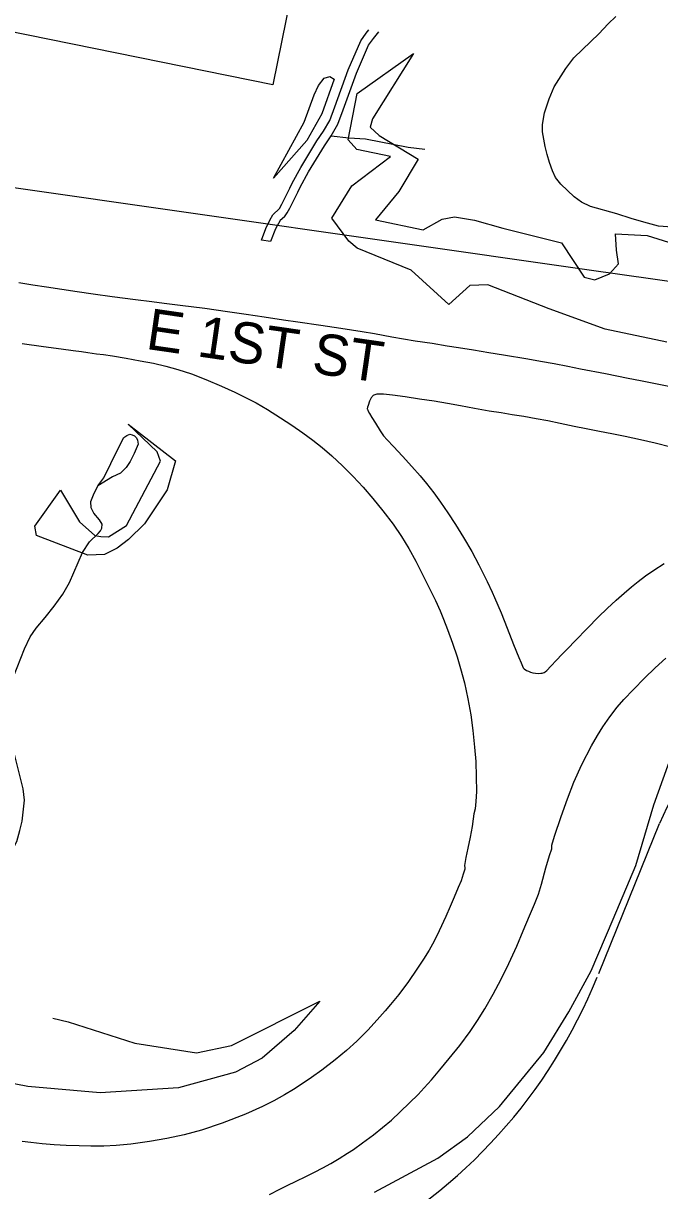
# Model space of a CAD drawing. Extents: x 1517485 to 1521905, y 636528 to 640355.
# Drawn here: x 1520638.4 to 1520886.6, y 638044.5 to 638499.8 of the extents above; entities that cross this region are included whole.
import ezdxf

# ---------------------------------------------------------------- set-up
doc = ezdxf.new("R2010")
doc.units = 0
for name, color, linetype in [('Exist Building', 7, 'Continuous'), ('Exist Hydro Stream or Body of Water', 7, 'Continuous'), ('Exist Right of Way Line', 7, 'Continuous'), ('Exist Roads EOP', 7, 'Continuous'), ('Exist Roads EOP Text', 7, 'Continuous'), ('Exist Vegetation Woods Line', 7, 'Continuous')]:
    doc.layers.add(name, color=color, linetype=linetype)

msp = doc.modelspace()

# ---------------------------------------------------------------- linework, layer by layer
at = {"layer": 'Exist Building'}
msp.add_lwpolyline([(1520578.55, 638507.74), (1520628.44, 638753.1), (1520785.56, 638721.15), (1520735.68, 638475.79)], close=True, dxfattribs=at)
at = {"layer": 'Exist Hydro Stream or Body of Water'}
for p, q in [((1520740.26, 638424.4), (1520741.25, 638425.86)), ((1520734.82, 638414.67), (1520731.3, 638415.27))]:
    msp.add_line(p, q, dxfattribs=at)
for points in [[(1520866.57, 638499.66), (1520869.57, 638502.49)], [(1520738.25, 638427.6), (1520739.26, 638429.35), (1520742.29, 638435.51), (1520743.29, 638437.53), (1520746.58, 638443.61), (1520752.94, 638453.93), (1520755.49, 638457.82), (1520757.92, 638461.98), (1520759.85, 638467.24), (1520765.15, 638481.67), (1520770.02, 638492.94), (1520772.17, 638496.03), (1520773.18, 638497.28)], [(1520741.25, 638425.86), (1520742.33, 638427.71), (1520745.4, 638433.98), (1520746.38, 638435.93), (1520749.59, 638441.87), (1520755.86, 638452.06), (1520758.44, 638455.99), (1520761.07, 638460.49), (1520763.1, 638466.04), (1520768.38, 638480.38), (1520773.07, 638491.24), (1520774.95, 638493.94), (1520777.06, 638496.55)], [(1520891.56, 638420.25), (1520886.13, 638420.7), (1520880.48, 638422.22), (1520875.53, 638423.69), (1520869.88, 638425.48), (1520859.66, 638428.33), (1520856.1, 638430.02), (1520853.26, 638432.13), (1520848.04, 638437.03), (1520845.95, 638439.72), (1520844.8, 638442.29), (1520843.69, 638445.51), (1520842.75, 638448.7), (1520842, 638451.81), (1520841.39, 638454.65), (1520840.88, 638457.53), (1520840.87, 638460.33), (1520841.75, 638464.85), (1520843.47, 638470.4), (1520845.53, 638475.09), (1520850.06, 638482.2), (1520853.09, 638486.31), (1520856.55, 638489.59), (1520862.85, 638495.74), (1520866.57, 638499.66)], [(1520758.44, 638455.99), (1520765.42, 638455.22), (1520771.8, 638454.72), (1520788.46, 638451.49), (1520795.05, 638450.71)], [(1520731.3, 638415.27), (1520733.01, 638419.8), (1520734.59, 638423.02), (1520735.68, 638425.14), (1520738.25, 638427.6)], [(1520740.26, 638424.4), (1520738.51, 638422.85), (1520736.76, 638419.71), (1520734.82, 638414.67)], [(1520665.7, 638315.85), (1520667.46, 638319.42), (1520669.75, 638322.58), (1520675.21, 638333.71), (1520677.51, 638338.26), (1520678.77, 638339.1), (1520679.87, 638339.64), (1520680.82, 638339.32), (1520681.72, 638338.87), (1520682.54, 638338.16), (1520682.92, 638337.19), (1520683.17, 638335.69), (1520681.55, 638332.02), (1520680.05, 638328.92), (1520678.46, 638326.54), (1520676.33, 638324.4), (1520673.21, 638322.96), (1520667.46, 638319.42)], [(1520668.1, 638306.19), (1520665.89, 638308.73), (1520664.82, 638310.89), (1520664.64, 638313.26), (1520665.7, 638315.85)], [(1520650.38, 638272.52), (1520653.83, 638277.19), (1520656.35, 638281.74), (1520661.38, 638293.42), (1520664.12, 638297.58), (1520667.57, 638300.89), (1520668.5, 638301.92), (1520668.93, 638302.93), (1520669.09, 638304.44), (1520668.1, 638306.19)], [(1520628.72, 638168.47), (1520630.1, 638171.66), (1520630.45, 638173.94), (1520631.42, 638175.53), (1520633.87, 638177.73), (1520634.78, 638178.74), (1520635.76, 638180.71), (1520636.98, 638184.96), (1520637.84, 638188.69), (1520638.84, 638196.88), (1520638.29, 638201.28), (1520634.9, 638214.77), (1520632.9, 638223.52), (1520631.75, 638232.09), (1520631.65, 638236.97), (1520632.89, 638240.82), (1520635.98, 638248.57), (1520638.83, 638255.82), (1520641.07, 638260.51), (1520643.43, 638263.96), (1520646.83, 638268.07), (1520650.38, 638272.52)]]:
    msp.add_lwpolyline(points, dxfattribs=at)
at = {"layer": 'Exist Right of Way Line'}
for p, q in [((1520592.71, 638441.73), (1520859.18, 638403.68)), ((1520859.18, 638403.68), (1520978.8, 638386.68)), ((1520862.88, 638129.25), (1520886.64, 638187.72))]:
    msp.add_line(p, q, dxfattribs=at)
for centre, radius, start, end in [((1520977.43, 638150.83), 98, 95.5211, 157.8844), ((1520668.65, 638206.43), 209, 297.9565, 337.8844)]:
    msp.add_arc(centre, radius, start, end, dxfattribs=at)
at = {"layer": 'Exist Roads EOP'}
for points in [[(1520636.62, 638398.74), (1520642.07, 638397.79), (1520647.36, 638396.98), (1520653.44, 638396.15), (1520659.41, 638395.19), (1520665.56, 638394.28), (1520673.07, 638393.28), (1520682.16, 638392.13), (1520688.56, 638391.29), (1520693.37, 638390.61), (1520699.54, 638389.89), (1520709.14, 638388.68), (1520717.98, 638387.4), (1520725.31, 638386.38), (1520732.29, 638385.3), (1520739.9, 638384.19), (1520745.5, 638383.45), (1520754.44, 638382.14), (1520762.28, 638380.95), (1520770.58, 638379.68), (1520775.4, 638378.84), (1520782.08, 638377.59), (1520791.3, 638376.04), (1520797.88, 638375.02), (1520803.74, 638374.08), (1520808.21, 638373.36), (1520814.02, 638372.43), (1520819.95, 638371.49), (1520825.72, 638370.58), (1520835.26, 638368.97), (1520840.15, 638368.09), (1520845.54, 638367.11), (1520850.77, 638366.1), (1520855.77, 638365.09), (1520865.51, 638363.18), (1520874.31, 638361.45), (1520879.11, 638360.52), (1520884.39, 638359.49), (1520893.43, 638357.62)], [(1520637.85, 638374.95), (1520646.25, 638373.81), (1520653.16, 638372.82), (1520657.8, 638372.15), (1520660.99, 638371.79), (1520663.57, 638371.45), (1520666.86, 638370.96), (1520669.7, 638370.6), (1520673.15, 638370.11), (1520678.44, 638369.16), (1520683.97, 638368.18), (1520689.1, 638367.23), (1520693.99, 638366.12), (1520698.64, 638364.82), (1520703.97, 638363.05), (1520709.6, 638360.94), (1520715.72, 638358.33), (1520720.87, 638356.02), (1520725.09, 638353.91), (1520729.19, 638351.76), (1520733.64, 638349.16), (1520738.71, 638346.01), (1520743.07, 638343.12), (1520747.38, 638340.13), (1520751.36, 638337.26), (1520754.92, 638334.4), (1520758.74, 638331.07), (1520762.95, 638327.21), (1520767.09, 638323.1), (1520770.92, 638318.94), (1520774.73, 638314.52), (1520778.66, 638309.71), (1520782.61, 638304.51), (1520785.95, 638299.65), (1520788.76, 638294.99), (1520791.52, 638289.98), (1520794.12, 638284.83), (1520796.75, 638279.59), (1520799.22, 638274.65), (1520801.03, 638270.73), (1520802.36, 638267.39), (1520803.89, 638263.4), (1520805.86, 638258.03), (1520807.65, 638252.73), (1520808.97, 638248.17), (1520810.43, 638242.57), (1520811.84, 638236.29), (1520812.92, 638230.12), (1520813.72, 638223.97), (1520814.42, 638217.54), (1520814.89, 638211.87), (1520815.07, 638205.94), (1520815.12, 638200.24), (1520814.96, 638196.25), (1520814.59, 638193.44), (1520814.19, 638191.55), (1520813.91, 638189.6), (1520813.45, 638186.6), (1520812.7, 638182.44), (1520811.84, 638178.13), (1520811.05, 638174.47), (1520810.62, 638172.08), (1520810.54, 638171.32), (1520810.57, 638170.37), (1520810.58, 638169.88), (1520810.5, 638169.49), (1520810.02, 638167.95), (1520809.13, 638165.31), (1520808.08, 638162.8), (1520806.5, 638159.02), (1520804.94, 638155.41), (1520803.16, 638151.48), (1520800.66, 638145.92), (1520798.65, 638141.85), (1520796.66, 638138.28), (1520794.5, 638134.77), (1520791.93, 638130.9), (1520788.61, 638126.09), (1520784.83, 638120.99), (1520781.62, 638117.07), (1520779.48, 638114.59), (1520776.48, 638111.16), (1520772.81, 638107.11), (1520768.5, 638102.78), (1520764.49, 638099.15), (1520760.04, 638095.5), (1520754.81, 638091.51), (1520750.76, 638088.67), (1520746.78, 638085.98), (1520743.79, 638083.98), (1520740.27, 638081.85), (1520736.11, 638079.55), (1520731.62, 638077.31), (1520725.01, 638074.36), (1520715.94, 638070.82), (1520707.92, 638068.13), (1520701.15, 638066.25), (1520694.41, 638064.82), (1520687.62, 638063.67), (1520680.31, 638062.64), (1520674.64, 638062.17), (1520669.76, 638061.93), (1520664.68, 638061.91), (1520660.08, 638061.96), (1520655.05, 638062.19), (1520650.36, 638062.4), (1520645.7, 638062.79), (1520641.25, 638063.31), (1520637.92, 638063.67)], [(1520891.02, 638334.54), (1520884.89, 638336.02), (1520879.11, 638337.41), (1520873.21, 638338.7), (1520868.02, 638339.68), (1520863.11, 638340.57), (1520857.91, 638341.62), (1520853.24, 638342.56), (1520847.8, 638343.74), (1520843.03, 638344.78), (1520838.42, 638345.61), (1520833.65, 638346.42), (1520829.11, 638347.17), (1520824.82, 638347.89), (1520820.14, 638348.61), (1520814.41, 638349.57), (1520808.87, 638350.59), (1520803.92, 638351.51), (1520798.6, 638352.41), (1520792.98, 638353.29), (1520787.38, 638354.12), (1520782.34, 638354.8), (1520778.94, 638355.16), (1520776.32, 638355.13), (1520775.89, 638355.06), (1520775.57, 638354.97), (1520775.07, 638354.74), (1520774.85, 638354.61), (1520774.64, 638354.46), (1520774.46, 638354.28), (1520774.28, 638354.06), (1520774.11, 638353.81), (1520773.49, 638352.44), (1520772.89, 638350.81), (1520772.66, 638350.14), (1520772.59, 638349.86), (1520772.57, 638349.63), (1520772.57, 638349.44), (1520772.61, 638349.27), (1520772.76, 638348.85), (1520773.38, 638347.69), (1520774.36, 638346.08), (1520775.75, 638343.81), (1520777.56, 638340.93), (1520778.89, 638338.98), (1520780.35, 638337.31), (1520782.78, 638334.74), (1520786.31, 638331), (1520789.89, 638327.02), (1520793.18, 638323.3), (1520795.63, 638320.39), (1520798.51, 638316.73), (1520801.13, 638313.1), (1520803.97, 638308.91), (1520806.98, 638304.37), (1520810.13, 638299.29), (1520813.3, 638293.86), (1520816.14, 638288.61), (1520819.3, 638282.09), (1520821.29, 638277.95), (1520822.23, 638275.93), (1520824.86, 638269.87), (1520827.14, 638263.97), (1520829.63, 638257.57), (1520831.7, 638252.43), (1520832.55, 638250.35), (1520833.08, 638249.04), (1520833.36, 638248.5), (1520833.5, 638248.3), (1520833.65, 638248.13), (1520833.8, 638248.02), (1520834.73, 638247.45), (1520835.41, 638247.09), (1520836.21, 638246.77), (1520837.14, 638246.52), (1520838.22, 638246.34), (1520839.32, 638246.26), (1520840.34, 638246.3), (1520840.8, 638246.37), (1520841.23, 638246.49), (1520841.61, 638246.65), (1520841.95, 638246.86), (1520842.62, 638247.41), (1520844.19, 638249.08), (1520846.45, 638251.45), (1520848.5, 638253.64), (1520850.73, 638255.89), (1520853.85, 638259.08), (1520858.37, 638263.74), (1520862.74, 638268.28), (1520866.12, 638271.63), (1520869.65, 638274.83), (1520872.79, 638277.55), (1520875.71, 638279.99), (1520878.19, 638282.13), (1520881.17, 638284.36), (1520884.34, 638286.49), (1520888.38, 638289.15)], [(1520734.44, 638043.06), (1520738.41, 638045.06), (1520741.36, 638046.56), (1520744.8, 638048.25), (1520748.59, 638050.06), (1520751.97, 638051.69), (1520755.21, 638053.36), (1520758.29, 638055.11), (1520761.61, 638057.08), (1520764.9, 638059.09), (1520767.15, 638060.6), (1520770.68, 638063.18), (1520774.99, 638066.33), (1520778.55, 638069.16), (1520781.95, 638072.07), (1520785.42, 638075.28), (1520789.03, 638078.73), (1520792.35, 638081.99), (1520794.8, 638084.6), (1520797.58, 638087.8), (1520800.88, 638091.69), (1520804.56, 638096.07), (1520808.68, 638101.18), (1520812.7, 638106.6), (1520815.53, 638110.85), (1520818.41, 638115.41), (1520821.64, 638121.14), (1520824.75, 638126.97), (1520827.78, 638133.12), (1520830.85, 638139.92), (1520833.42, 638145.9), (1520835.84, 638151.7), (1520837.77, 638156.27), (1520839.35, 638160.2), (1520840.57, 638164.08), (1520842.27, 638170.47), (1520843.67, 638175.23), (1520844.52, 638177.82), (1520844.59, 638178.3), (1520844.51, 638178.82), (1520844.55, 638179.23), (1520845.65, 638182.83), (1520848.23, 638190.47), (1520850.63, 638197.39), (1520853.21, 638203.89), (1520856.33, 638210.75), (1520860.01, 638218.03), (1520862.39, 638222.09), (1520864.48, 638225.43), (1520867.24, 638229.38), (1520870.08, 638233.14), (1520872.7, 638236.04), (1520876.39, 638240.03), (1520880.71, 638244.46), (1520884.92, 638248.43), (1520889.04, 638252.22)]]:
    msp.add_lwpolyline(points, dxfattribs=at)
at = {"layer": 'Exist Vegetation Woods Line'}
for points in [[(1520889.49, 638375.43), (1520865.36, 638380.59), (1520843.49, 638388.52), (1520819.66, 638397.81), (1520812.59, 638397.58), (1520804.44, 638390.12), (1520789.74, 638403.49), (1520768.64, 638412.1), (1520765.4, 638414.81), (1520758.75, 638423.79), (1520766.55, 638436.49), (1520781.58, 638447.83), (1520768.51, 638450.64), (1520765.09, 638454.39), (1520768.58, 638472.47), (1520790.62, 638488.04), (1520774.6, 638462.58), (1520773.67, 638459.33), (1520777.22, 638456.03), (1520792.47, 638446.79), (1520784.83, 638434.2), (1520775.75, 638423.16), (1520794.39, 638419.25), (1520801.83, 638423.4), (1520806.62, 638424.33), (1520814.35, 638423.02), (1520825.39, 638419.88), (1520848.29, 638414.25), (1520857.15, 638400.82), (1520861.32, 638399.74), (1520867.11, 638402.15), (1520870.6, 638406.01), (1520869.8, 638411.29), (1520869.43, 638417.66), (1520881.75, 638417.1), (1520892.15, 638413.77)], [(1520759.6, 638477.98), (1520754.88, 638464.55), (1520748.91, 638454.18), (1520735.96, 638439.47), (1520747.9, 638461.22), (1520751.8, 638471.95), (1520753.57, 638475.54), (1520755.74, 638478.42), (1520757.99, 638479.13), (1520759.6, 638477.98)], [(1520694.51, 638317.87), (1520685.64, 638304.64), (1520679.34, 638298.48), (1520674.91, 638295.12), (1520670.06, 638292.68), (1520663.52, 638292.38), (1520643.48, 638300.03), (1520642.87, 638303.7), (1520652.85, 638317.73), (1520660.3, 638305.33), (1520666.3, 638300.07), (1520668.58, 638299.71), (1520671.61, 638299.49), (1520678.55, 638303.9), (1520691.91, 638329.01), (1520690.59, 638332.71), (1520679.2, 638343.46), (1520697.68, 638329.24), (1520694.51, 638317.87)], [(1520775.44, 638043.96), (1520800.09, 638057.16), (1520811.71, 638065.52), (1520824.19, 638077.3), (1520841.4, 638098.42), (1520851.2, 638114.29), (1520859.95, 638130.31), (1520868.44, 638150.4), (1520877.35, 638171.36), (1520884.38, 638195.02), (1520891.61, 638215.25), (1520895.85, 638221.65), (1520906.1, 638232.7), (1520919.29, 638241.61), (1520935.14, 638245.55), (1520953.48, 638251.83), (1520963.71, 638255.09), (1520971.81, 638256.14), (1520976.73, 638254.73), (1520982.78, 638251.76), (1520988.6, 638248.9), (1520995.05, 638245.75), (1521002.19, 638242.73), (1521023.27, 638237.65)], [(1520754.04, 638118.45), (1520744.04, 638106.93), (1520731.51, 638096.19), (1520721.19, 638090.72), (1520698.89, 638084.63), (1520668.32, 638082.73), (1520640.13, 638085.09), (1520624.63, 638088.08), (1520602.26, 638095.33), (1520559.71, 638112.1), (1520531.98, 638123.41), (1520533.92, 638133.39), (1520555.77, 638126.72), (1520568.7, 638122.77)], [(1520649.85, 638111.78), (1520655.85, 638110.34), (1520681.9, 638102.04), (1520705.92, 638098.28), (1520719.64, 638101.1), (1520754.04, 638118.45)]]:
    msp.add_lwpolyline(points, dxfattribs=at)

# ---------------------------------------------------------------- texts
at = {"layer": 'Exist Roads EOP Text'}
msp.add_text('E 1ST ST', height=16, rotation=351.7511, dxfattribs=at).set_placement((1520685.77, 638372.9))

doc.saveas('drawing.dxf')
